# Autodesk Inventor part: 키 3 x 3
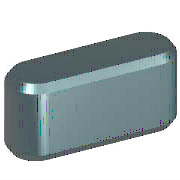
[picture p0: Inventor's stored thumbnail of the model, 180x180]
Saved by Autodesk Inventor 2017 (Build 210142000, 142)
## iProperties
Created: 2012-02
Part Number: 키 3 x 3
Material: 강철, 연강
Description: 키 및 해당 키홈
Document SubType Name: Modeling
Standard: KS B 1311
Designer: mduedu
Standards Organization: KS
Language: ko-KR
Size Designation: 3 x 3 x 12
Categories: <MemberInstance><Categories><Category DisplayName="샤프트 부품" InternalName="7f7aeb1f-a693-4053-b835-cee3144e0d98" Mnemonic="SHFT"><Category DisplayName="키" Interna
Density: 7.86 g/cm^3
Mass: 0.790122 g
Surface Area: 1.42216 cm^2
Volume: 0.100524 cm^3
Appearance: 노란색
IsCustomPart: 1
Author: mduedu
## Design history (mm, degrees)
workplane "Work Plane1"
workplane "Work Plane2"
sketch "스케치1"
  geometry: L1 (1.5, 1.5)-(10.5, 1.5); L2 (10.5, -1.5)-(1.5, -1.5); L3 (0, 9.4)-(0, -7.4) reference; L4 (-5, 0)-(30, 0) reference; L5 (12, 0)-(12, 7); A1 r 1.5 centre (1.5, 0) between (1.5, 1.5) and (1.5, -1.5); A2 r 1.5 centre (10.5, 0) between (10.5, -1.5) and (10.5, 1.5)
  constraints: 6 end point, 5 point on circle, 4 tangent, 3 point on line, 2 centre point, 1 horizontal, 1 parallel, 1 perpendicular
  dimensions: "d0" = 1.5 radius of A1 (= 0.5 x PB); "d13" = 1.5 radius of A2 (= 0.5 x PB); "d14" = 12 distance between parallel lines of L5 L3 (= NLG)
extrude "본체1" new body sketch "스케치1" taper "d3" = 0 deg; stored distance "d4" = 10
workplane "Work Plane3"
body "Solid1"
chamfer "모따기1" distance "d8" = 0.25 (= PHH); stored, may be unused: second distance "d9" = 0.25 (= PHH), angle "d15" = 45 deg
other parameters: "d1" = -1.8 (= -PNT), "d2" = 1.2 (= PH - PNT), "NLG" = 12 [user parameter; used in 3 equation terms], "PB" = 3 [user parameter; used in 2 equation terms], "PNT" = 1.8 [user parameter; used in 2 equation terms], "PH" = 3 [user parameter; used in 1 equation term], "PHH" = 0.25 [user parameter; used in 2 equation terms], "d10" = 0, "d16" = 0, "d17" = 0, "d18" = 0, "WDMIN" = 8 [user parameter], "PLB2" = 12 (= NLG) [user parameter], "PLB1" = 12 (= NLG) [user parameter], "RR" = 0.08 [user parameter], "PUEB" = 1.4 [user parameter]
